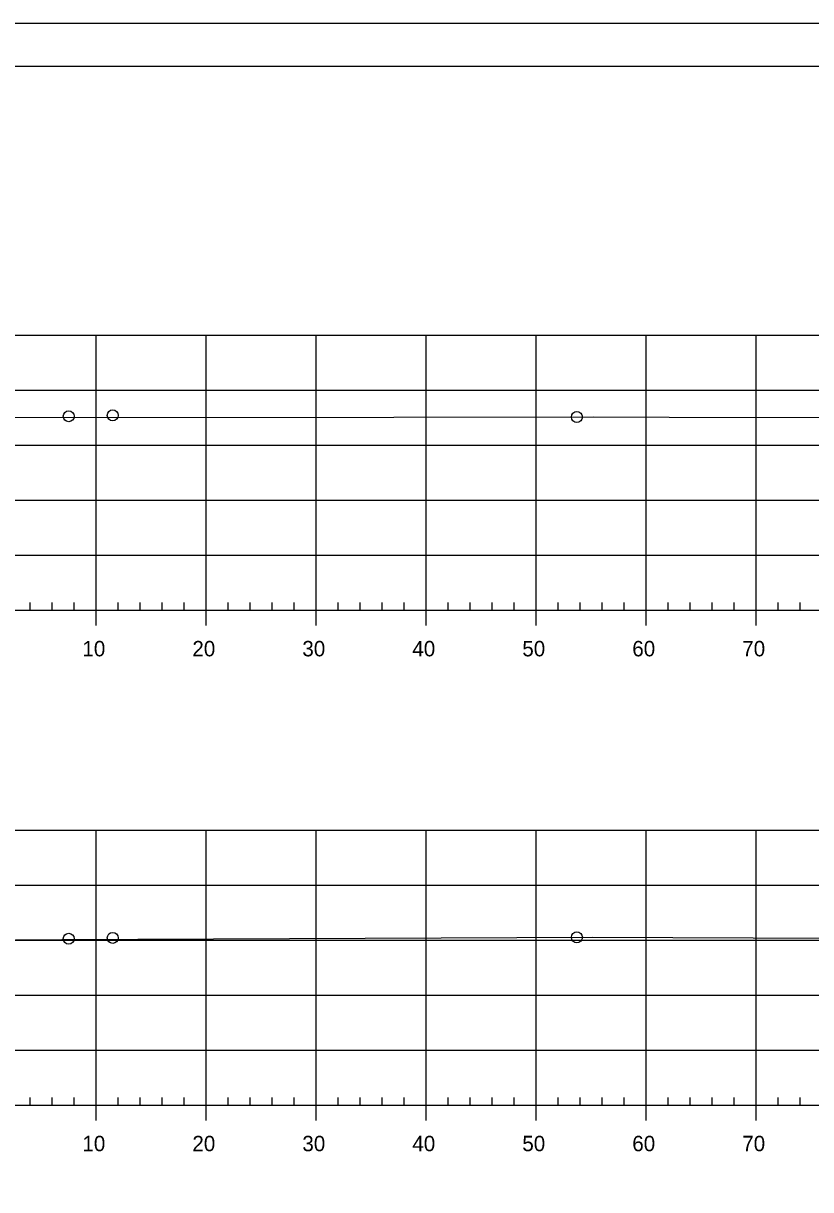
# Model space of a CAD drawing. Extents: x 1359801 to 1362404, y 372415 to 374228.
# Drawn here: x 1361823.3 to 1361894.9, y 372841.9 to 372947.9 of the extents above; entities that cross this region are included whole.
import ezdxf

# ---------------------------------------------------------------- set-up
doc = ezdxf.new("R2010")
doc.units = 0
for name, color, linetype in [('S_DRG_PT_SYM', 7, 'Continuous'), ('S_MAILBOX', 7, 'Continuous'), ('S_PRIMARY_CTL', 7, 'Continuous'), ('S_SHOULDER', 7, 'Continuous'), ('S_UTL_PT_SYM', 7, 'Continuous'), ('S_WATER_UTILITIES', 7, 'Continuous')]:
    doc.layers.add(name, color=color, linetype=linetype)

msp = doc.modelspace()

# ---------------------------------------------------------------- linework, layer by layer
at = {"layer": 'S_DRG_PT_SYM'}
for points in [[(1361822.48, 372912.11), (1361856.96, 372912.14), (1361875.14, 372912.15), (1361881.99, 372912.14), (1361924.73, 372912.1), (1361930.42, 372911.87), (1361932.8, 372911.77), (1361933.77, 372911.63), (1361935.94, 372911.34), (1361942.24, 372910.01), (1361943.82, 372909.64), (1361946.94, 372908.98), (1361948.01, 372908.76), (1361951.86, 372909.59), (1361952.24, 372909.67), (1361953.1, 372909.87), (1361963.05, 372912.05), (1361964.89, 372912.39)], [(1361822.55, 372864.61), (1361826.77, 372864.63), (1361875.04, 372864.84), (1361918.76, 372864.66), (1361924.71, 372864.64), (1361925.51, 372864.6), (1361932.71, 372864.3), (1361933.32, 372864.23), (1361935.79, 372863.91), (1361939.13, 372863.33), (1361942.54, 372862.68), (1361946.11, 372862.07), (1361947.18, 372861.91), (1361948.18, 372862.09), (1361950.64, 372862.65), (1361960.25, 372865.04), (1361962.81, 372865.68), (1361963.87, 372865.76), (1361964.89, 372865.85)]]:
    msp.add_lwpolyline(points, dxfattribs=at)
at = {"layer": 'S_MAILBOX'}
for p, q in [((1361674.89, 372919.58), (1361964.89, 372919.58)), ((1361829.89, 372894.58), (1361829.89, 372919.58)), ((1361839.89, 372894.58), (1361839.89, 372919.58)), ((1361849.89, 372894.58), (1361849.89, 372919.58)), ((1361859.89, 372894.58), (1361859.89, 372919.58)), ((1361869.89, 372894.58), (1361869.89, 372919.58)), ((1361879.89, 372894.58), (1361879.89, 372919.58)), ((1361889.89, 372894.58), (1361889.89, 372919.58)), ((1361674.89, 372914.58), (1361964.89, 372914.58)), ((1361674.89, 372909.58), (1361964.89, 372909.58)), ((1361674.89, 372904.58), (1361964.89, 372904.58)), ((1361674.89, 372899.58), (1361964.89, 372899.58)), ((1361674.89, 372894.58), (1361964.89, 372894.58)), ((1361674.89, 372874.58), (1361964.89, 372874.58)), ((1361829.89, 372849.58), (1361829.89, 372874.58)), ((1361839.89, 372849.58), (1361839.89, 372874.58)), ((1361849.89, 372849.58), (1361849.89, 372874.58)), ((1361859.89, 372849.58), (1361859.89, 372874.58)), ((1361869.89, 372849.58), (1361869.89, 372874.58)), ((1361879.89, 372849.58), (1361879.89, 372874.58)), ((1361889.89, 372849.58), (1361889.89, 372874.58)), ((1361674.89, 372869.58), (1361964.89, 372869.58)), ((1361674.89, 372864.58), (1361964.89, 372864.58)), ((1361674.89, 372859.58), (1361964.89, 372859.58)), ((1361674.89, 372854.58), (1361964.89, 372854.58)), ((1361674.89, 372849.58), (1361964.89, 372849.58))]:
    msp.add_line(p, q, dxfattribs=at)
at = {"layer": 'S_SHOULDER'}
msp.add_line((1361649.49, 372947.94), (1361982.82, 372947.94), dxfattribs=at)
for points in [[(1361649.48, 372947.94), (1361982.82, 372947.94), (1361982.82, 372734.6), (1361649.48, 372734.6)], [(1361895.81, 372944.04), (1361895.81, 372934.16), (1361931.54, 372934.16), (1361931.54, 372931.24), (1361954.74, 372931.24), (1361954.74, 372906.91), (1361978.07, 372906.91), (1361978.07, 372738.58), (1361661.89, 372738.58), (1361661.89, 372944.04)]]:
    msp.add_lwpolyline(points, close=True, dxfattribs=at)
for centre in [(1361827.39, 372912.21), (1361831.39, 372912.29), (1361873.59, 372912.14), (1361831.39, 372864.78), (1361873.59, 372864.83), (1361827.39, 372864.7)]:
    msp.add_circle(centre, 0.5, dxfattribs=at)
at = {"layer": 'S_UTL_PT_SYM'}
msp.add_line((1361661.89, 372944.04), (1361978.07, 372944.04), dxfattribs=at)
at = {"layer": 'S_WATER_UTILITIES'}
for p, q in [((1361823.89, 372894.58), (1361823.89, 372895.28)), ((1361825.89, 372894.58), (1361825.89, 372895.28)), ((1361827.89, 372894.58), (1361827.89, 372895.28)), ((1361831.89, 372894.58), (1361831.89, 372895.28)), ((1361833.89, 372894.58), (1361833.89, 372895.28)), ((1361835.89, 372894.58), (1361835.89, 372895.28)), ((1361837.89, 372894.58), (1361837.89, 372895.28)), ((1361841.89, 372894.58), (1361841.89, 372895.28)), ((1361843.89, 372894.58), (1361843.89, 372895.28)), ((1361845.89, 372894.58), (1361845.89, 372895.28)), ((1361847.89, 372894.58), (1361847.89, 372895.28)), ((1361851.89, 372894.58), (1361851.89, 372895.28)), ((1361853.89, 372894.58), (1361853.89, 372895.28)), ((1361855.89, 372894.58), (1361855.89, 372895.28)), ((1361857.89, 372894.58), (1361857.89, 372895.28)), ((1361861.89, 372894.58), (1361861.89, 372895.28)), ((1361863.89, 372894.58), (1361863.89, 372895.28)), ((1361865.89, 372894.58), (1361865.89, 372895.28)), ((1361867.89, 372894.58), (1361867.89, 372895.28)), ((1361871.89, 372894.58), (1361871.89, 372895.28)), ((1361873.89, 372894.58), (1361873.89, 372895.28)), ((1361875.89, 372894.58), (1361875.89, 372895.28)), ((1361877.89, 372894.58), (1361877.89, 372895.28)), ((1361881.89, 372894.58), (1361881.89, 372895.28)), ((1361883.89, 372894.58), (1361883.89, 372895.28)), ((1361885.89, 372894.58), (1361885.89, 372895.28)), ((1361887.89, 372894.58), (1361887.89, 372895.28)), ((1361891.89, 372894.58), (1361891.89, 372895.28)), ((1361893.89, 372894.58), (1361893.89, 372895.28)), ((1361674.89, 372894.58), (1361964.89, 372894.58)), ((1361829.89, 372893.18), (1361829.89, 372894.58)), ((1361839.89, 372893.18), (1361839.89, 372894.58)), ((1361849.89, 372893.18), (1361849.89, 372894.58)), ((1361859.89, 372893.18), (1361859.89, 372894.58)), ((1361869.89, 372893.18), (1361869.89, 372894.58)), ((1361879.89, 372893.18), (1361879.89, 372894.58)), ((1361889.89, 372893.18), (1361889.89, 372894.58)), ((1361674.89, 372849.58), (1361964.89, 372849.58)), ((1361823.89, 372849.58), (1361823.89, 372850.28)), ((1361825.89, 372849.58), (1361825.89, 372850.28)), ((1361827.89, 372849.58), (1361827.89, 372850.28)), ((1361829.89, 372848.18), (1361829.89, 372849.58)), ((1361831.89, 372849.58), (1361831.89, 372850.28)), ((1361833.89, 372849.58), (1361833.89, 372850.28)), ((1361835.89, 372849.58), (1361835.89, 372850.28)), ((1361837.89, 372849.58), (1361837.89, 372850.28)), ((1361839.89, 372848.18), (1361839.89, 372849.58)), ((1361841.89, 372849.58), (1361841.89, 372850.28)), ((1361843.89, 372849.58), (1361843.89, 372850.28)), ((1361845.89, 372849.58), (1361845.89, 372850.28)), ((1361847.89, 372849.58), (1361847.89, 372850.28)), ((1361849.89, 372848.18), (1361849.89, 372849.58)), ((1361851.89, 372849.58), (1361851.89, 372850.28)), ((1361853.89, 372849.58), (1361853.89, 372850.28)), ((1361855.89, 372849.58), (1361855.89, 372850.28)), ((1361857.89, 372849.58), (1361857.89, 372850.28)), ((1361859.89, 372848.18), (1361859.89, 372849.58)), ((1361861.89, 372849.58), (1361861.89, 372850.28)), ((1361863.89, 372849.58), (1361863.89, 372850.28)), ((1361865.89, 372849.58), (1361865.89, 372850.28)), ((1361867.89, 372849.58), (1361867.89, 372850.28)), ((1361869.89, 372848.18), (1361869.89, 372849.58)), ((1361871.89, 372849.58), (1361871.89, 372850.28)), ((1361873.89, 372849.58), (1361873.89, 372850.28)), ((1361875.89, 372849.58), (1361875.89, 372850.28)), ((1361877.89, 372849.58), (1361877.89, 372850.28)), ((1361879.89, 372848.18), (1361879.89, 372849.58)), ((1361881.89, 372849.58), (1361881.89, 372850.28)), ((1361883.89, 372849.58), (1361883.89, 372850.28)), ((1361885.89, 372849.58), (1361885.89, 372850.28)), ((1361887.89, 372849.58), (1361887.89, 372850.28)), ((1361889.89, 372848.18), (1361889.89, 372849.58)), ((1361891.89, 372849.58), (1361891.89, 372850.28)), ((1361893.89, 372849.58), (1361893.89, 372850.28))]:
    msp.add_line(p, q, dxfattribs=at)

# ---------------------------------------------------------------- texts
at = {"layer": 'S_PRIMARY_CTL'}
for s, p in [('10', (1361828.63, 372890.38)), ('20', (1361838.63, 372890.38)), ('30', (1361848.63, 372890.38)), ('40', (1361858.63, 372890.38)), ('50', (1361868.63, 372890.38)), ('60', (1361878.63, 372890.38)), ('70', (1361888.63, 372890.38)), ('10', (1361828.63, 372845.38)), ('20', (1361838.63, 372845.38)), ('30', (1361848.63, 372845.38)), ('40', (1361858.63, 372845.38)), ('50', (1361868.63, 372845.38)), ('60', (1361878.63, 372845.38)), ('70', (1361888.63, 372845.38))]:
    msp.add_text(s, height=1.4, dxfattribs=at).set_placement(p)

doc.saveas('drawing.dxf')
